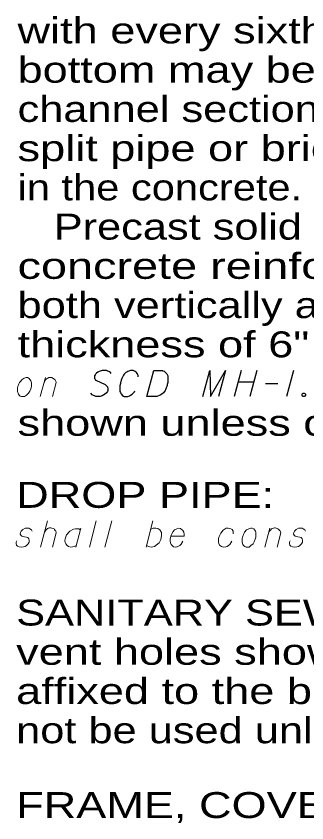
# Model space of a CAD drawing. Extents: x 1083.1 to 1117.1, y 697.4 to 741.4.
# Drawn here: x 1104.978 to 1106.726, y 730.897 to 735.749 of the extents above; entities that cross this region are included whole.
import ezdxf

# ---------------------------------------------------------------- set-up
doc = ezdxf.new("R2010")
doc.units = 0
doc.header["$LTSCALE"] = 0.062
doc.layers.add('1', color=7, linetype='Continuous', lineweight=13)

msp = doc.modelspace()

# ---------------------------------------------------------------- linework, layer by layer
at = {"layer": '1', "lineweight": 25}
for p, q in [((1106.33025, 733.61842), (1106.28817, 733.46108)), ((1106.42442, 733.61842), (1106.38233, 733.46108)), ((1106.64492, 733.61842), (1106.60283, 733.46108)), ((1106.31175, 733.54908), (1106.40583, 733.54908)), ((1106.4765, 733.54042), (1106.55083, 733.54042))]:
    msp.add_line(p, q, dxfattribs=at)
at = {"layer": '1'}
for p, q in [((1105.12242, 733.46108), (1105.15342, 733.57508)), ((1105.125, 732.55567), (1105.16592, 732.713)), ((1105.41867, 732.55567), (1105.4595, 732.713)), ((1105.5115, 732.55567), (1105.55242, 732.713)), ((1105.75933, 732.55567), (1105.80017, 732.713)), ((1105.36658, 732.66967), (1105.33683, 732.55567)), ((1106.47283, 732.55567), (1106.50383, 732.66967))]:
    msp.add_line(p, q, dxfattribs=at)
at = {"layer": '1', "lineweight": 25}
for points in [[(1105.54858, 733.59983), (1105.54608, 733.60483), (1105.53992, 733.60975), (1105.53492, 733.61225), (1105.52875, 733.61475), (1105.52008, 733.61725), (1105.51017, 733.61842), (1105.504, 733.61842), (1105.49408, 733.61725), (1105.47792, 733.611), (1105.46925, 733.60733), (1105.46058, 733.60108), (1105.45442, 733.59617), (1105.45192, 733.59242), (1105.4495, 733.58625), (1105.44825, 733.58125), (1105.44825, 733.57633), (1105.4495, 733.57017), (1105.45192, 733.56517), (1105.45567, 733.56025), (1105.45692, 733.559), (1105.51267, 733.533), (1105.52383, 733.52308), (1105.52625, 733.51933), (1105.5275, 733.51683), (1105.53, 733.50817), (1105.53, 733.50325), (1105.52875, 733.49825), (1105.52625, 733.49208), (1105.52133, 733.48342), (1105.50892, 733.4735), (1105.50525, 733.471), (1105.49533, 733.46608), (1105.48908, 733.46358), (1105.48292, 733.46233), (1105.473, 733.46108), (1105.46925, 733.46108), (1105.45692, 733.46233), (1105.4495, 733.46483), (1105.44325, 733.46733), (1105.43458, 733.47225), (1105.42592, 733.48092)], [(1105.71208, 733.57883), (1105.71208, 733.5825), (1105.71083, 733.5875), (1105.70958, 733.59242), (1105.70717, 733.59742), (1105.70592, 733.59983), (1105.70217, 733.60483), (1105.6985, 733.60858), (1105.6935, 733.61225), (1105.68858, 733.61475), (1105.68117, 733.61725), (1105.67492, 733.61842), (1105.67242, 733.61842), (1105.665, 733.61725), (1105.65633, 733.61475), (1105.65017, 733.61225), (1105.64275, 733.60858), (1105.6365, 733.60483), (1105.63033, 733.59983), (1105.62658, 733.59492), (1105.62292, 733.58875), (1105.61917, 733.5825), (1105.613, 733.57017), (1105.60925, 733.559), (1105.60683, 733.55033), (1105.60558, 733.54533), (1105.60433, 733.53917), (1105.60183, 733.5255), (1105.60058, 733.51567), (1105.60058, 733.5045), (1105.60183, 733.49208), (1105.60433, 733.48592), (1105.608, 733.47967), (1105.6105, 733.476), (1105.6155, 733.46983), (1105.62292, 733.46358), (1105.62783, 733.46233), (1105.63525, 733.46108), (1105.64025, 733.46108), (1105.6415, 733.46108), (1105.65017, 733.46233), (1105.66008, 733.46483), (1105.66625, 733.46858), (1105.67492, 733.47475), (1105.68233, 733.48217), (1105.68858, 733.48958), (1105.691, 733.49458)], [(1106.09983, 733.46108), (1106.142, 733.61842), (1106.14692, 733.46108), (1106.23617, 733.61842), (1106.194, 733.46108)]]:
    msp.add_lwpolyline(points, dxfattribs=at)
for points in [[(1105.80625, 733.61842), (1105.84833, 733.61842), (1105.85708, 733.61725), (1105.86075, 733.616), (1105.86692, 733.6135), (1105.87067, 733.611), (1105.87442, 733.60858), (1105.88058, 733.60233), (1105.88433, 733.59742), (1105.8905, 733.585), (1105.8905, 733.55775), (1105.88925, 733.54533), (1105.888, 733.53917), (1105.88675, 733.533), (1105.8855, 733.52675), (1105.88308, 733.52058), (1105.88058, 733.51317), (1105.87567, 733.502), (1105.87317, 733.49708), (1105.86325, 733.48342), (1105.85458, 733.476), (1105.84467, 733.46983), (1105.8335, 733.46483), (1105.82358, 733.46233), (1105.81242, 733.46108), (1105.76417, 733.46108)], [(1106.70442, 733.48217), (1106.71058, 733.48217), (1106.71433, 733.47967), (1106.71808, 733.47475), (1106.71808, 733.46858), (1106.71433, 733.46358), (1106.71058, 733.46108), (1106.70442, 733.46108), (1106.70075, 733.46358), (1106.697, 733.46858), (1106.697, 733.47475), (1106.70075, 733.47967)]]:
    msp.add_lwpolyline(points, close=True, dxfattribs=at)
at = {"layer": '1'}
for points in [[(1105.03817, 733.57508), (1105.04683, 733.57508), (1105.05675, 733.57017), (1105.06667, 733.5565), (1105.06792, 733.55033), (1105.06917, 733.54408), (1105.06917, 733.53917), (1105.06917, 733.52058), (1105.06542, 733.50817), (1105.05925, 733.49333), (1105.05183, 733.48092), (1105.03942, 733.46983), (1105.02825, 733.46108), (1105.00967, 733.46108), (1105.00225, 733.46358), (1104.99483, 733.46983), (1104.99108, 733.476), (1104.98617, 733.49083), (1104.98617, 733.51317), (1104.98858, 733.52058), (1104.99358, 733.53667), (1104.9985, 733.54533), (1105.001, 733.55033), (1105.01342, 733.56392), (1105.02575, 733.57142)], [(1106.38867, 732.66967), (1106.39733, 732.66967), (1106.40725, 732.66475), (1106.41717, 732.65108), (1106.41833, 732.64492), (1106.41958, 732.63867), (1106.41958, 732.63375), (1106.41958, 732.61517), (1106.41592, 732.60275), (1106.40967, 732.58792), (1106.40225, 732.5755), (1106.38992, 732.56442), (1106.37875, 732.55567), (1106.36017, 732.55567), (1106.35275, 732.55817), (1106.34525, 732.56442), (1106.34158, 732.57058), (1106.33658, 732.58542), (1106.33658, 732.60775), (1106.33908, 732.61517), (1106.34408, 732.63125), (1106.349, 732.63992), (1106.3515, 732.64492), (1106.36383, 732.6585), (1106.37625, 732.666)]]:
    msp.add_lwpolyline(points, close=True, dxfattribs=at)
for points in [[(1105.14592, 733.54783), (1105.14967, 733.554), (1105.15467, 733.5615), (1105.15833, 733.56517), (1105.16333, 733.57017), (1105.16825, 733.57258), (1105.17442, 733.57508), (1105.18067, 733.57633), (1105.18558, 733.57633), (1105.19175, 733.57508), (1105.19675, 733.57258), (1105.20167, 733.57017), (1105.20667, 733.56642), (1105.21158, 733.5615), (1105.21408, 733.55775), (1105.21658, 733.55283), (1105.21908, 733.54658), (1105.19675, 733.46108)], [(1105.073, 732.65108), (1105.06925, 732.65975), (1105.06058, 732.666), (1105.05317, 732.66842), (1105.042, 732.66967), (1105.03208, 732.66842), (1105.01725, 732.661), (1105.00733, 732.65108), (1105.00358, 732.64242), (1105.00233, 732.6325), (1105.00483, 732.62633), (1105.00983, 732.62258), (1105.01225, 732.62133), (1105.01975, 732.61892), (1105.02842, 732.61767), (1105.04075, 732.61517), (1105.04825, 732.61267), (1105.05442, 732.60525), (1105.05692, 732.59658), (1105.05567, 732.58542), (1105.05067, 732.5755), (1105.04075, 732.56442), (1105.03208, 732.55942), (1105.02217, 732.55692), (1105.00983, 732.55567), (1104.99492, 732.55692), (1104.985, 732.56192), (1104.98008, 732.56808), (1104.97758, 732.57675), (1104.97758, 732.58542), (1104.98133, 732.59283)], [(1105.14858, 732.64617), (1105.15225, 732.65108), (1105.15725, 732.6585), (1105.16092, 732.66225), (1105.16342, 732.66475), (1105.16717, 732.66717), (1105.17083, 732.66842), (1105.17458, 732.66967), (1105.17825, 732.67092), (1105.18692, 732.67092), (1105.19317, 732.66967), (1105.20058, 732.66717), (1105.2055, 732.66475), (1105.20925, 732.661), (1105.213, 732.65608), (1105.21542, 732.65233), (1105.21667, 732.64983), (1105.21917, 732.64492), (1105.21917, 732.64117), (1105.19567, 732.55567)], [(1105.36408, 732.65975), (1105.35542, 732.666), (1105.33442, 732.666), (1105.322, 732.6635), (1105.29967, 732.65108), (1105.28108, 732.62883), (1105.27242, 732.60525), (1105.27117, 732.59283), (1105.27242, 732.583), (1105.27617, 732.57425), (1105.28358, 732.56442), (1105.29225, 732.55817), (1105.30592, 732.55567), (1105.31583, 732.55692), (1105.32575, 732.55817), (1105.33933, 732.56558)], [(1105.78658, 732.661), (1105.80142, 732.66842), (1105.8175, 732.66967), (1105.82992, 732.66717), (1105.84108, 732.65975), (1105.851, 732.64367), (1105.85225, 732.62258), (1105.84725, 732.60033), (1105.83733, 732.58175), (1105.81008, 732.55942), (1105.789, 732.55567), (1105.77292, 732.55817), (1105.76175, 732.56558)], [(1105.908, 732.62133), (1105.98725, 732.62133), (1105.9885, 732.63375), (1105.986, 732.64492), (1105.98108, 732.65608), (1105.96617, 732.66717), (1105.95383, 732.66842), (1105.94392, 732.666), (1105.93025, 732.6585), (1105.92158, 732.64983), (1105.91417, 732.63625), (1105.90917, 732.62633), (1105.90425, 732.60525), (1105.90425, 732.59167), (1105.9055, 732.5805), (1105.90917, 732.57058), (1105.92408, 732.55692), (1105.934, 732.55567), (1105.94392, 732.55692), (1105.94517, 732.55692), (1105.96125, 732.56442), (1105.96992, 732.57308), (1105.97367, 732.57925), (1105.97483, 732.5805), (1105.98108, 732.59167)], [(1106.28333, 732.63625), (1106.28208, 732.65108), (1106.27592, 732.661), (1106.2685, 732.666), (1106.25358, 732.66842), (1106.24, 732.66842), (1106.22267, 732.65733), (1106.209, 732.63867), (1106.19908, 732.62017), (1106.19533, 732.6065), (1106.19533, 732.58542), (1106.19658, 732.578), (1106.20158, 732.56808), (1106.21275, 732.55817), (1106.22508, 732.55567), (1106.23875, 732.55692), (1106.24617, 732.55942), (1106.26225, 732.57058), (1106.27467, 732.59167)], [(1106.49642, 732.64242), (1106.50017, 732.64858), (1106.50508, 732.65608), (1106.50883, 732.65975), (1106.51375, 732.66475), (1106.51875, 732.66717), (1106.52492, 732.66967), (1106.53108, 732.67092), (1106.53608, 732.67092), (1106.54225, 732.66967), (1106.54717, 732.66717), (1106.55217, 732.66475), (1106.55708, 732.661), (1106.56208, 732.65608), (1106.56458, 732.65233), (1106.567, 732.64742), (1106.5695, 732.64117), (1106.54717, 732.55567)], [(1106.71692, 732.65108), (1106.71325, 732.65975), (1106.70458, 732.666), (1106.69708, 732.66842), (1106.686, 732.66967), (1106.67608, 732.66842), (1106.66117, 732.661), (1106.65125, 732.65108), (1106.64758, 732.64242), (1106.64633, 732.6325), (1106.64883, 732.62633), (1106.65375, 732.62258), (1106.65625, 732.62133), (1106.66367, 732.61892), (1106.67233, 732.61767), (1106.68475, 732.61517), (1106.69217, 732.61267), (1106.69833, 732.60525), (1106.70083, 732.59658), (1106.69958, 732.58542), (1106.69467, 732.5755), (1106.68475, 732.56442), (1106.67608, 732.55942), (1106.66617, 732.55692), (1106.65375, 732.55567), (1106.63892, 732.55692), (1106.629, 732.56192), (1106.624, 732.56808), (1106.62158, 732.57675), (1106.62158, 732.58542), (1106.62525, 732.59283)]]:
    msp.add_lwpolyline(points, dxfattribs=at)

# ---------------------------------------------------------------- texts
for s, width, p in [('with every sixth course a stretcher course.  The 6" [150]', 1.3, (1104.98617, 735.58508)), ('bottom may be precast or cast-in-place concrete.  The bottom', 1.3, (1104.98617, 735.34908)), ('channel section shall be built with concrete and lined with', 1.25, (1104.98617, 735.11308)), ('split pipe or brick except curved channels may be formed', 1.3, (1104.98617, 734.87708)), ('in the concrete.', 1.2, (1104.98617, 734.64108)), ('   Precast solid concrete radial blocks or cast-in-place', 1.25, (1104.98617, 734.40508)), ('concrete reinforced with #4 [#13M] bars on 12" [300] centers', 1.35, (1104.98617, 734.16908)), ('both vertically and horizontally, may be used with a wall', 1.25, (1104.98617, 733.93308)), ('thickness of 6" [150] or greater.  Precast manholes detailed', 1.3, (1104.98617, 733.69708)), ('shown unless otherwise specified in the plans.', 1.3, (1104.98617, 733.22508)), ('DROP PIPE:', 1.3, (1104.97758, 732.79167)), ('SANITARY SEWER:', 1.25, (1104.97758, 732.08367)), ('vent holes shown here and shall include a sealing gasket', 1.3, (1104.97758, 731.84767)), ('affixed to the bearing surface.  Bolt-down covers shall', 1.3, (1104.97758, 731.61167)), ('not be used unless specified in the plans.', 1.25, (1104.97758, 731.37567)), ('FRAME, COVER, AND STEPS:', 1.3, (1104.97758, 730.92567))]:
    msp.add_text(s, height=0.156, dxfattribs=dict(at, width=width)).set_placement(p)

doc.saveas('drawing.dxf')
